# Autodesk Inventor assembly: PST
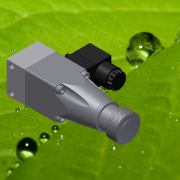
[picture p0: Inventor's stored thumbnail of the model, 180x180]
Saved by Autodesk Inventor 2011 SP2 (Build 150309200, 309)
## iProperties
Created: 2013-12
Part Number: PST
Document SubType Name: Assembly
Designer: dorohin
Author: dorohin
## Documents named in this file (5)
- C:\Users\dorohin\Documents\Inventor\CTR-KV0797\PST.iam
- C:\Users\dorohin\Documents\Inventor\CTR-KV0797\PSP_.ipt
- C:\Users\dorohin\Documents\Inventor\CTR-KV0797\ECA_B_10.ipt
- C:\Users\dorohin\Documents\Inventor\Content Center Files\R2011\ru-RU\GOST 11738-84\Винт M5-6gx45 ГОСТ 11738-84.ipt
- C:\Users\dorohin\Documents\Inventor\CTR-KV0797\PSP_-G14.ipt
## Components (7 placed, 4 different names)
1. PSP_:1 — Вставка:1, Угол:1, Вставка:3, Вставка:4, Вставка:5, Вставка:6, Вставка:7, Угол:2
2. ECA/B/10:1 — Вставка:1, Угол:1
3. Винт ГОСТ 11738-84 M 5x45:1 — Вставка:6
4. Винт ГОСТ 11738-84 M 5x45:2 — Вставка:5
5. Винт ГОСТ 11738-84 M 5x45:3 — Вставка:3
6. Винт ГОСТ 11738-84 M 5x45:4 — Вставка:4
7. PSP_-G14:1 — Вставка:7, Угол:2
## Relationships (8: Insert 6, Angle 2)
- Вставка:1 [Insert]: PSP_:1 ↔ ECA/B/10:1
- Угол:1 [Angle]: PSP_:1 ↔ ECA/B/10:1
- Вставка:3 [Insert]: PSP_:1 ↔ Винт ГОСТ 11738-84 M 5x45:3
- Вставка:4 [Insert]: PSP_:1 ↔ Винт ГОСТ 11738-84 M 5x45:4
- Вставка:5 [Insert]: PSP_:1 ↔ Винт ГОСТ 11738-84 M 5x45:2
- Вставка:6 [Insert]: PSP_:1 ↔ Винт ГОСТ 11738-84 M 5x45:1
- Вставка:7 [Insert]: PSP_:1 ↔ PSP_-G14:1
- Угол:2 [Angle]: PSP_:1 ↔ PSP_-G14:1
